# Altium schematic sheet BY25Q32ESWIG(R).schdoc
size 127 x 101 mm
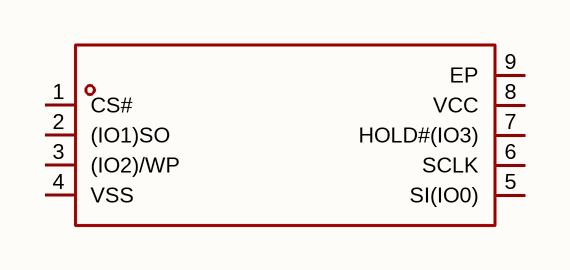
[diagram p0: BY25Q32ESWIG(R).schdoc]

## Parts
U?  by25q32eswig(r)  [WSON-8_L6.0-W5.0-P1.27-TL-EP4.0]  (value not drawn)

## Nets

Not connected (* = marked no-connect by the designer): U? 1(CS#) 2((IO1)SO) 3((IO2)/WP) 4(VSS) 5(SI(IO0)) 6(SCLK) 7(HOLD#(IO3)) 8(VCC) 9(EP)

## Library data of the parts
U? = by25q32eswig(r): 接口类型:SPI;存储容量:32Mbit;时钟频率(fc):120MHz;; Manufacturer: BOYAMICRO(博雅); AddInBom: yes; Interface: SPI; Memory Size: 32Mbit; Clock Frequency: 120MHz; Voltage - Supply: 2.7V~3.6V; Standby Supply Current: 2uA; Program / Erase Cycles: 100000次; Page Programming Time (Tpp): 450us; Block Erase Time(tBE): 180ms@(64KB); Data Retention - TDR (Year): 20年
